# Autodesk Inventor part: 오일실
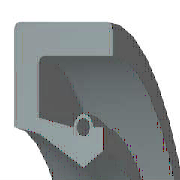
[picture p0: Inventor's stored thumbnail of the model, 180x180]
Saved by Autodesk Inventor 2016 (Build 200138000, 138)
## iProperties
IsCustomPart: 1
Created: 2015-12
Part Number: 오일실
Material: 고무
Description: 오일-실
Document SubType Name: Modeling
Standard: KS B 2804
Designer: mdu
Standards Organization: KS
Language: ko-KR
Size Designation: S - 15 30 7
Categories: <MemberInstance><Categories><Category DisplayName="샤프트 부품" InternalName="7f7aeb1f-a693-4053-b835-cee3144e0d98" Mnemonic="SHFT"><Category DisplayName="실링" Intern
Density: 0.93 g/cm^3
Mass: 1.64364 g
Surface Area: 26.6454 cm^2
Volume: 1.76736 cm^3
Appearance: 고무 - 검은색 - 버전 1.1
Author: mdu
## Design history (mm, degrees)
revolve "본체" stored, may be unused: angle "d17" = 90 deg
revolve "스프링1" stored, may be unused: angle "d18" = 90 deg
body "Solid1"
sketch "스케치1"
  geometry: L1 (0, 15)-(7, 15); L2 (7, 15)-(7, 13.75); L3 (7, 13.75)-(1.75, 13.75); L4 (0, 15)-(0, 9.6); L5 (0, 9.6)-(1.75, 9.25); L6 (1.75, 9.25)-(4.9, 7.5); L7 (4.9, 7.5)-(0, 7.5); L8 (6.3, 8.375)-(6.3, 9.6); L9 (0, 0)-(9.586, 0) reference; L10 (4.9, 7.5)-(6.3, 8.375); L11 (0, 18)-(0, -3) reference; L12 (-1.917, 0)-(11.503, 0) reference; L13 (4.2, 9.6)-(1.75, 10.09); L14 (1.75, 10.09)-(1.75, 13.75); L15 (6.3, 9.6)-(5.6, 9.6); C1 r 0.455 at (4.9, 9.6); A1 r 0.7 centre (4.9, 9.6) between (5.6, 9.6) and (4.2, 9.6)
  constraints: 26 end point, 5 horizontal alignment, 4 perpendicular, 2 centre point, 2 collinear, 2 horizontal, 2 parallel, 2 point on circle, 2 point on line, 2 vertical alignment, 1 coincident
  dimensions: "d0" = 30 diameter of L1 L9 (= SD2); "d1" = 16.75 diameter of L8.start L9 (= ABDM); "d2" = 1.25 distance of L1.end L2.end (computed from SD); "d3" = 0.91 diameter of C1 (= SPDI); "d4" = 1.4 diameter of A1 (= SPDA); "d5" = 15 diameter of L6.end L9 (= NND); "d6" = 18.5 diameter of L5.end L9 (= TKDM); "d7" = 19.2 diameter of L4.end L9 (= HLDM); "d8" = 4.9 distance from line of C1.centre L4 (= SPDST); "d9" = 6.3 distance between parallel lines of L8 L4 (= SDI); "d10" = 7 distance between parallel lines of L2 L4 (= SWDT); "d12" = 1.75 distance between parallel lines of L14 L4 (= SD)
fillet "모깎기1" dims "d11" = 0.3 (= RR)
other parameters: "SD2" = 30 [user parameter; used in 1 equation term], "SWDT" = 7 [user parameter; used in 1 equation term], "RR" = 0.3 [user parameter; used in 1 equation term], "SD" = 1.75 [user parameter; used in 2 equation terms], "NND" = 15 [user parameter; used in 1 equation term], "SPDA" = 1.4 [user parameter; used in 1 equation term], "SPDI" = 0.91 [user parameter; used in 1 equation term], "TKDM" = 18.5 [user parameter; used in 1 equation term], "HLDM" = 19.2 [user parameter; used in 1 equation term], "ABDM" = 16.75 [user parameter; used in 1 equation term], "SDI" = 6.3 [user parameter; used in 1 equation term], "SPDST" = 4.9 [user parameter; used in 1 equation term], "d13" = 0, "d14" = 0, "d15" = 0, "LAB" = 0.35 [user parameter]
